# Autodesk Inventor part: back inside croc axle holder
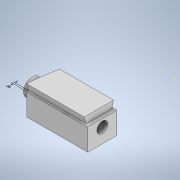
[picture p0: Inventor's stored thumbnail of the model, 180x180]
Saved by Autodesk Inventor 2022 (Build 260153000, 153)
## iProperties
Created: 2021-07
Part Number: back inside croc axle holder
Material: Generic
Document SubType Name: Modeling
Designer: garre
Density: 1 g/cm^3
Appearance: Default
Author: garre
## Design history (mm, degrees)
node "Annotations"
  node "Linear Dimension 1" dims "d3" = 1.27 (derived)
derived "croc skate axle holders.ipt"
sketch "Sketch1"
  geometry: 1 further point
feature "back inside::croc skate axle holders.ipt" dims "d0" = 10
tag "TaggingFeature1"
body "Solid1"
other parameters: "d1" = 2.29148 (derived), "d2" = 7.74156 (derived)
